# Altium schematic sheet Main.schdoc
size 297 x 196 mm
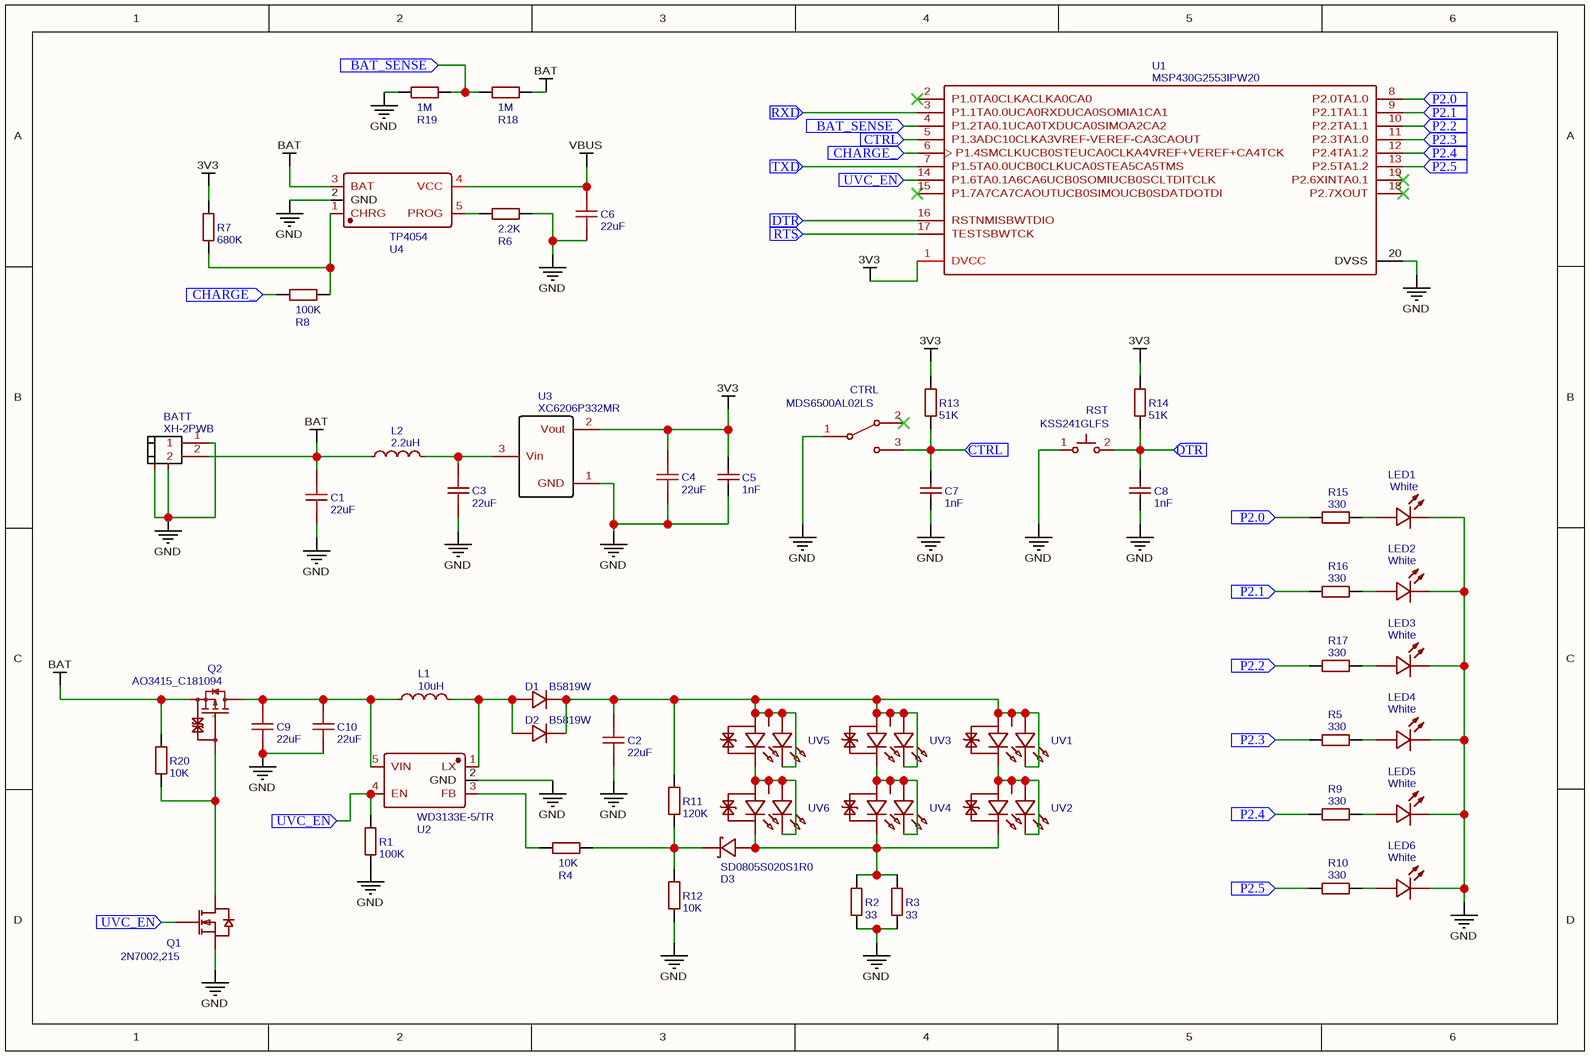
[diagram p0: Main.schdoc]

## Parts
BATT  XH-2PWB  [CONN-SMD_2P-P2.50_XH-2PWB]
C1  22uF  [C0805]
C2  22uF  [C0805]
C3  22uF  [C0805]
C4  22uF  [C0805]
C5  1nF  [C0805]
C6  22uF  [C0805]
C7  1nF  [C0805]
C8  1nF  [C0805]
C9  22uF  [C0805]
C10  22uF  [C0805]
CTRL  MDS6500AL02LS  [SW-TH_MDS6500AL02LS]
D1  B5819W  [SOD-123_L2.8-W1.8-LS3.7-RD]
D2  B5819W  [SOD-123_L2.8-W1.8-LS3.7-RD]
D3  SD0805S020S1R0  [D0805-RD]
L1  10uH  [IND-SMD_L3.0-W3.0]
L2  2.2uH  [L0805]
LED1  White  [LED0805-FD]
LED2  White  [LED0805-FD]
LED3  White  [LED0805-FD]
LED4  White  [LED0805-FD]
LED5  White  [LED0805-FD]
LED6  White  [LED0805-FD]
Q1  2N7002,215  [SOT-23_L2.9-W1.3-P1.90-LS2.4-BR]
Q2  AO3415_C181094  [SOT-23-3_L2.9-W1.3-P1.90-LS2.4-BR]
R1  100K  [R0805]
R2  33  [R0805]
R3  33  [R0805]
R4  10K  [R0805]
R5  330  [R0805]
R6  2.2K  [R0805]
R7  680K  [R0805]
R8  100K  [R0805]
R9  330  [R0805]
R10  330  [R0805]
R11  120K  [R0805]
R12  10K  [R0805]
R13  51K  [R0805]
R14  51K  [R0805]
R15  330  [R0805]
R16  330  [R0805]
R17  330  [R0805]
R18  1M  [R0805]
R19  1M  [R0805]
R20  10K  [R0805]
RST  KSS241GLFS  [KEY-SMD_KSS-2G]
U1  MSP430G2553IPW20  [TSSOP-20_L6.5-W4.4-P0.65-LS6.4-BL]
U2  WD3133E-5/TR  [TSOT-23-5_L2.9-W1.6-P0.95-LS2.8-BL]
U3  XC6206P332MR  [SOT-23-3_L2.9-W1.6-P1.90-LS2.8-BR]
U4  TP4054  [SOT-23-5_L3.0-W1.7-P0.95-LS2.8-BR]
UV1  F.35.00041  [LED-SMD_5P-L3.5-W3.5_UVC-UVA]  (value not drawn)
UV2  F.35.00041  [LED-SMD_5P-L3.5-W3.5_UVC-UVA]  (value not drawn)
UV3  F.35.00041  [LED-SMD_5P-L3.5-W3.5_UVC-UVA]  (value not drawn)
UV4  F.35.00041  [LED-SMD_5P-L3.5-W3.5_UVC-UVA]  (value not drawn)
UV5  F.35.00041  [LED-SMD_5P-L3.5-W3.5_UVC-UVA]  (value not drawn)
UV6  F.35.00041  [LED-SMD_5P-L3.5-W3.5_UVC-UVA]  (value not drawn)

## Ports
BAT_SENSE (in), CHARGE_ (in), CTRL (in), DTR (in), P2.0 (in), P2.1 (in), P2.2 (in), P2.3 (in), P2.4 (in), P2.5 (in), RTS (in), RXD (in), TXD (in), UVC_EN (in)

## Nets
3V3: C4.2 C5.2 R7.2 R13.2 R14.2 U1.1(DVCC) U3.2(Vout)
BAT: BATT.2 C1.2 L2.1 Q2.2(S) R18.2 R20.2 U4.3(BAT)
GND: BATT.1 BATT.3 BATT.4 C1.1 C2.1 C3.1 C4.1 C5.1 C6.1 C7.1 C8.1 C9.1 C10.1 CTRL.1(COM) LED1.2(K) LED2.2(K) LED3.2(K) LED4.2(K) LED5.2(K) LED6.2(K) Q1.2(S) R1.1 R2.1 R3.1 R6.1 R12.1 R19.1 RST.1 U1.20(DVSS) U2.2(GND) U3.1(GND) U4.2(GND)
VBUS: C6.2 U4.4(VCC)
BAT_SENSE: R18.1 R19.2 U1.4(P1.2TA0.1UCA0TXDUCA0SIMOA2CA2) ; port BAT_SENSE
CHARGE_: R8.2 U1.6(P1.4SMCLKUCB0STEUCA0CLKA4VREF+VEREF+CA4TCK) ; port CHARGE_
CTRL: C7.2 CTRL.3(ON) R13.1 U1.5(P1.3ADC10CLKA3VREF-VEREF-CA3CAOUT) ; port CTRL
DTR: C8.2 R14.1 RST.2 U1.16(RSTNMISBWTDIO) ; port DTR
P2.0: R15.1 U1.8(P2.0TA1.0) ; port P2.0
P2.1: R16.1 U1.9(P2.1TA1.1) ; port P2.1
P2.2: R17.1 U1.10(P2.2TA1.1) ; port P2.2
P2.3: R5.1 U1.11(P2.3TA1.0) ; port P2.3
P2.4: R9.1 U1.12(P2.4TA1.2) ; port P2.4
P2.5: R10.1 U1.13(P2.5TA1.2) ; port P2.5
RTS: U1.17(TESTSBWTCK) ; port RTS
RXD: U1.3(P1.1TA0.0UCA0RXDUCA0SOMIA1CA1) ; port RXD
TXD: U1.7(P1.5TA0.0UCB0CLKUCA0STEA5CA5TMS) ; port TXD
UVC_EN: Q1.1(G) R1.2 U1.14(P1.6TA0.1A6CA6UCB0SOMIUCB0SCLTDITCLK) U2.4(EN) ; port UVC_EN
NetC2_2: C2.2 D1.1(-) D2.1(-) R11.2 UV1.1(UVA+) UV1.2(UVA-) UV1.3(UVC+) UV1.5(EP) UV3.1(UVA+) UV3.2(UVA-) UV3.3(UVC+) UV3.5(EP) UV5.1(UVA+) UV5.2(UVA-) UV5.3(UVC+) UV5.5(EP)
NetC3_2: C3.2 L2.2 U3.3(Vin)
NetC9_2: C9.2 C10.2 L1.1 Q2.3(D) U2.5(VIN)
NetD1_2: D1.2(+) D2.2(+) L1.2 U2.1(LX)
NetD3_1: D3.1(K) R4.1 R11.1 R12.2
NetD3_2: D3.2(A) R2.2 R3.2 UV2.4(UVC-) UV4.4(UVC-) UV6.4(UVC-)
NetLED1_1: LED1.1(A) R15.2
NetLED2_1: LED2.1(A) R16.2
NetLED3_1: LED3.1(A) R17.2
NetLED4_1: LED4.1(A) R5.2
NetLED5_1: LED5.1(A) R9.2
NetLED6_1: LED6.1(A) R10.2
NetQ1_3: Q1.3(D) Q2.1(G) R20.1
NetR4_2: R4.2 U2.3(FB)
NetR6_2: R6.2 U4.5(PROG)
NetR7_1: R7.1 R8.1 U4.1(CHRG)
NetUV1_4: UV1.4(UVC-) UV2.1(UVA+) UV2.2(UVA-) UV2.3(UVC+) UV2.5(EP)
NetUV3_4: UV3.4(UVC-) UV4.1(UVA+) UV4.2(UVA-) UV4.3(UVC+) UV4.5(EP)
NetUV5_4: UV5.4(UVC-) UV6.1(UVA+) UV6.2(UVA-) UV6.3(UVC+) UV6.5(EP)

Not connected (* = marked no-connect by the designer): CTRL 2(NC)*; U1 2(P1.0TA0CLKACLKA0CA0)* 15(P1.7A7CA7CAOUTUCB0SIMOUCB0SDATDOTDI)* 18(P2.7XOUT)* 19(P2.6XINTA0.1)*

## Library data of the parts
BATT = XH-2PWB: BOM_Manufacturer: BOOMELE
C1-C4 C6 C9 C10 = 22uF: BOM_Manufacturer: SAMSUNG; BOM_Manufacturer Part: CL21A226MAQNNNE; nameAlias: Capacitance
C5 C7 C8 = 1nF: BOM_Manufacturer Part: CL21B102KBCNNNC; BOM_Manufacturer: SAMSUNG; nameAlias: Capacitance
CTRL = MDS6500AL02LS: BOM_Manufacturer: C&K; Contributor: LCSC
D1 D2 = B5819W: BOM_Manufacturer: CJ
D3 = SD0805S020S1R0: BOM_Manufacturer: AVX; Contributor: LCSC; BOM_Paste Type: Extended Part
L1 = 10uH: BOM_Manufacturer: Chilisin Elec; BOM_Manufacturer Part: LVS303012H-100M-N; nameAlias: Inductance; Contributor: LCSC
L2 = 2.2uH: BOM_Manufacturer Part: CMI201209U2R2KT; BOM_Manufacturer: FH; nameAlias: Inductance
LED1-LED6 = White: BOM_Manufacturer: KENTO; BOM_Manufacturer Part: whiteLEDSMD
Q1 = 2N7002,215: BOM_Manufacturer: Nexperia
Q2 = AO3415_C181094: BOM_Manufacturer: Hottech; BOM_Manufacturer Part: AO3415; Contributor: LCSC
R1 R8 = 100K: BOM_Manufacturer: UniOhm; BOM_Manufacturer Part: 0805W8F1003T5E; nameAlias: Resistance (Ohms)
R2 R3 = 33: BOM_Manufacturer: UniOhm; BOM_Manufacturer Part: 0805W8J0330T5E; nameAlias: Resistance (Ohms)
R4 R12 R20 = 10K: BOM_Manufacturer: UniOhm; BOM_Manufacturer Part: 0805W8F1002T5E; nameAlias: Resistance (Ohms)
R5 R9 R10 R15-R17 = 330: BOM_Manufacturer: UniOhm; BOM_Manufacturer Part: 0805W8F3300T5E; nameAlias: Resistance (Ohms)
R6 = 2.2K: BOM_Manufacturer: UniOhm; BOM_Manufacturer Part: 0805W8F2201T5E; nameAlias: Resistance (Ohms)
R7 = 680K: BOM_Manufacturer: UniOhm; BOM_Manufacturer Part: 0805W8F6803T5E; nameAlias: Resistance (Ohms)
R11 = 120K: BOM_Manufacturer: UniOhm; BOM_Manufacturer Part: 0805W8F1203T5E; nameAlias: Resistance (Ohms)
R13 R14 = 51K: BOM_Manufacturer: UniOhm; BOM_Manufacturer Part: 0805W8F5102T5E; nameAlias: Resistance (Ohms)
R18 R19 = 1M: BOM_Manufacturer: UniOhm; BOM_Manufacturer Part: 0805W8F1004T5E; nameAlias: Resistance (Ohms)
RST = KSS241GLFS: BOM_Manufacturer: C&K; Contributor: LCSC
U1 = MSP430G2553IPW20: BOM_Manufacturer: TI
U2 = WD3133E-5/TR: BOM_Manufacturer: Will Semicon; Contributor: LCSC
U3 = XC6206P332MR: BOM_Manufacturer: TOREX
U4 = TP4054: BOM_Manufacturer: TOPPOWER; sourceId: dx642CAWU; Contributor: kyle.hu.gz
UV1-UV6 = F.35.00041: BOM_Manufacturer: TUOZHAN; Contributor: LCSC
